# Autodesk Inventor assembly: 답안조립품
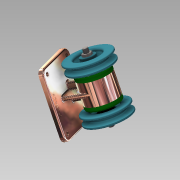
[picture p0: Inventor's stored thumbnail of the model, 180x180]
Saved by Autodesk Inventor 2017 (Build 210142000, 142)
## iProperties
Part Number: 답안조립품
Material: 일반
Document SubType Name: Assembly
Designer: 603-17
Author: 603-17
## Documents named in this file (10)
- C:\Users\603-17\Desktop\490904V1001\답안조립품.iam
- C:\Users\603-17\Desktop\490904V1001\V-벨트풀리.ipt
- C:\Users\603-17\Desktop\490904V1001\너트 M10x1.ipt
- C:\Users\603-17\Desktop\490904V1001\베어링 6004.ipt
- C:\Users\603-17\Desktop\490904V1001\볼트 M4.ipt
- C:\Users\603-17\Desktop\490904V1001\오일 실 17 30 5.ipt
- C:\Users\603-17\Desktop\490904V1001\축.ipt
- C:\Users\603-17\Desktop\490904V1001\커버.ipt
- C:\Users\603-17\Desktop\490904V1001\키 5 x 5 x 12.ipt
- C:\Users\603-17\Desktop\490904V1001\본체.ipt
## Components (2 placed, 1 different names)
1. V-벨트풀리:1
2. V-벨트풀리:2
